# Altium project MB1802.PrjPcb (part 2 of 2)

## Sheet Audio_Codec.SchDoc: Audio_Codec
size A4; Date: Not used; ApprovedBy: Not used; CheckedBy: Not used; Author: Not used; CompanyName: STMicroelectronics; DrawnBy: Not used; Engineer: Not used; Organization: Not used; Address1: Not used; Address2: Not used; Address3: Not used; Address4: Not used; DocumentNumber: Not used; Revision: Not used; SheetNumber: 5; SheetTotal: 11
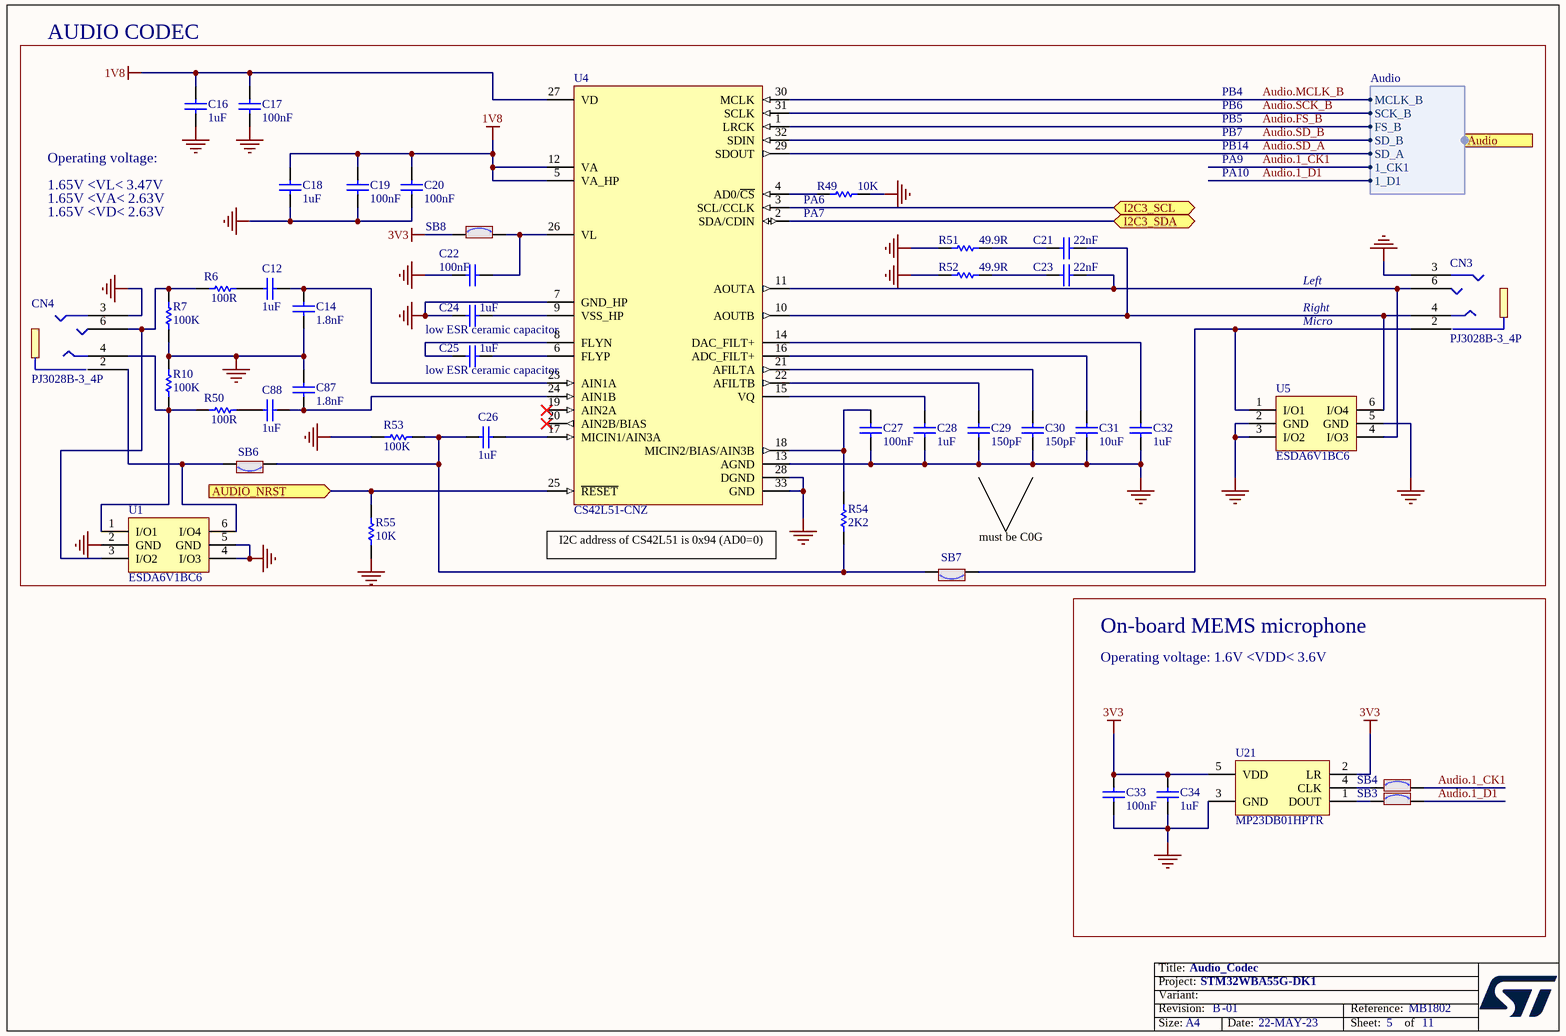
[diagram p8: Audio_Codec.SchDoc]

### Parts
C12  value 1uF  [C0402]  (hidden comment: Capacitor)
C14  value 1.8nF  [C0402]  (hidden comment: Capacitor)
C16  value 1uF  [C0402]  (hidden comment: Capacitor)
C17  value 100nF  [C0402]  (hidden comment: Capacitor)
C18  value 1uF  [C0402]  (hidden comment: Capacitor)
C19  value 100nF  [C0402]  (hidden comment: Capacitor)
C20  value 100nF  [C0402]  (hidden comment: Capacitor)
C21  value 22nF  [C0603]  (hidden comment: Capacitor)
C22  value 100nF  [C0402]  (hidden comment: Capacitor)
C23  value 22nF  [C0603]  (hidden comment: Capacitor)
C24  value 1uF  [C0402]  (hidden comment: Capacitor)
C25  value 1uF  [C0402]  (hidden comment: Capacitor)
C26  value 1uF  [C0402]  (hidden comment: Capacitor)
C27  value 100nF  [C0402]  (hidden comment: Capacitor)
C28  value 1uF  [C0402]  (hidden comment: Capacitor)
C29  value 150pF  [C0402]  (hidden comment: Capacitor)
C30  value 150pF  [C0402]  (hidden comment: Capacitor)
C31  value 10uF  [C0603]  (hidden comment: Capacitor)
C32  value 1uF  [C0402]  (hidden comment: Capacitor)
C33  value 100nF  [C0402]  (hidden comment: Capacitor)
C34  value 1uF  [C0402]  (hidden comment: Capacitor)
C87  value 1.8nF  [C0402]  (hidden comment: Capacitor)
C88  value 1uF  [C0402]  (hidden comment: Capacitor)
CN3  value PJ3028B-3_4P  [CON_PHONE-JACK-3P5_HY_PJ3028B]  (hidden comment: Jack_PJ3028B-3_4P)
CN4  value PJ3028B-3_4P  [CON_PHONE-JACK-3P5_HY_PJ3028B]  (hidden comment: Jack_PJ3028B-3_4P)
R6  value 100R  [R0402]  (hidden comment: Resistor)
R7  value 100K  [R0402]  (hidden comment: Resistor)
R10  value 100K  [R0402]  (hidden comment: Resistor)
R49  value 10K  [R0402]  (hidden comment: Resistor)
R50  value 100R  [R0402]  (hidden comment: Resistor)
R51  value 49.9R  [R0603]  (hidden comment: Resistor)
R52  value 49.9R  [R0603]  (hidden comment: Resistor)
R53  value 100K  [R0402]  (hidden comment: Resistor)
R54  value 2K2  [R0402]  (hidden comment: Resistor)
R55  value 10K  [R0402]  (hidden comment: Resistor)
SB3  (no value)  [SOLDER-BRIDGE_R0603-0R]
SB4  (no value)  [SOLDER-BRIDGE_R0603-0R]
SB6  (no value)  [SOLDER-BRIDGE_R0603-0R]
SB7  (no value)  [SOLDER-BRIDGE_R0603-0R]
SB8  SB_ON  [SOLDER-BRIDGE_R0603-0R]  (value not drawn)
U1  ESDA6V1BC6  [ESD_SOT23-6L]
U4  CS42L51-CNZ  [ICC_QFN32-EPAD_5X5_P050]
U5  ESDA6V1BC6  [ESD_SOT23-6L]
U21  value MP23DB01HPTR  [MIC_STM_MP23DB01MMTR]  (hidden comment: MP23DB01MMTR)

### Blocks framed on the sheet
AUDIO CODEC: C12 C14 C16-C32 C87 C88 CN3 CN4 R6 R7 R10 R49-R55 SB6-SB8 U1 U4 U5
On-board MEMS microphone: C33 C34 SB3 SB4 U21

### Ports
Audio (harness Audio), AUDIO_NRST (in), I2C3_SCL (bidir), I2C3_SDA (bidir)

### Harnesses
Audio: MCLK_B, 1_CK1, FS_B, SD_A, SCK_B, SD_B, 1_D1

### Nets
1V8: C16.2 C17.2 C18.2 C19.2 C20.2 U4.5(VA_HP) U4.12(VA) U4.27(VD)
3V3: C33.2 C34.1 SB8.1 U21.2(LR) U21.5(VDD)
GND: C14.1 C16.1 C17.1 C18.1 C19.1 C20.1 C22.2 C24.1 C27.1 C28.1 C29.1 C30.1 C31.1 C32.1 C33.1 C34.2 C87.2 CN3.3 CN4.3 R7.2 R10.1 R49.2 R51.2 R52.2 R53.2 R55.2 U1.2(GND) U1.4(I/O3) U1.5(GND) U4.7(GND_HP) U4.13(AGND) U4.28(DGND) U4.33(GND) U5.2(GND) U5.3(I/O2) U5.5(GND) U21.3(GND)
ARD_ADC.A4: U4.2(SDA/CDIN) ; port I2C3_SDA
ARD_ADC.A5: U4.3(SCL/CCLK) ; port I2C3_SCL
Audio.1_CK1: SB4.2 ; port Audio.1_CK1  [project net ARD.D9_TIM]
Audio.1_D1: SB3.2 ; port Audio.1_D1  [project net ARD.D6_TIM]
Audio.FS_B: U4.1(LRCK) ; port Audio.FS_B
Audio.MCLK_B: U4.30(MCLK) ; port Audio.MCLK_B
Audio.SCK_B: U4.31(SCLK) ; port Audio.SCK_B
Audio.SD_A: U4.29(SDOUT) ; port Audio.SD_A
Audio.SD_B: U4.32(SDIN) ; port Audio.SD_B
NetC12_1: C12.1 R6.2
NetC12_2: C12.2 C14.2 U4.23(AIN1A)
NetC21_1: C21.1 R51.1
NetC21_2: C21.2 CN3.4 U4.10(AOUTB) U5.6(I/O4)
NetC22_1: C22.1 SB8.2 U4.26(VL)
NetC23_1: C23.1 R52.1
NetC23_2: C23.2 CN3.6 U4.11(AOUTA) U5.4(I/O3)
NetC24_2: C24.2 U4.9(VSS_HP)
NetC25_1: C25.1 U4.8(FLYN)
NetC25_2: C25.2 U4.6(FLYP)
NetC26_1: C26.1 R53.1 R54.1 SB6.1 SB7.2
NetC26_2: C26.2 U4.17(MICIN1/AIN3A)
NetC27_2: C27.2 R54.2 U4.18(MICIN2/BIAS/AIN3B)
NetC28_2: C28.2 U4.15(VQ)
NetC29_2: C29.2 U4.22(AFILTB)
NetC30_2: C30.2 U4.21(AFILTA)
NetC31_2: C31.2 U4.16(ADC_FILT+)
NetC32_2: C32.2 U4.14(DAC_FILT+)
NetC87_1: C87.1 C88.2 U4.24(AIN1B)
NetC88_1: C88.1 R50.2
NetCN2_7: R55.1 U4.25(~{RESET}) ; port AUDIO_NRST
NetCN3_2: CN3.2 SB7.1 U5.1(I/O1)
NetCN4_2: CN4.2 SB6.2 U1.6(I/O4)
NetCN4_4: CN4.4 R10.2 R50.1 U1.1(I/O1)
NetCN4_6: CN4.6 R6.1 R7.1 U1.3(I/O2)
NetR49_1: R49.1 U4.4(AD0/~{CS})
NetSB3_1: SB3.1 U21.1(DOUT)
NetSB4_1: SB4.1 U21.4(CLK)

Not connected (* = marked no-connect by the designer): U4 19(AIN2A)* 20(AIN2B/BIAS)*

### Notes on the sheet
- PB6
- PB4
- (near C16) Operating voltage:
- PB14
- PB7
- PB5
- PA9
- PA10
- 1.65V <VL< 3.47V
- 1.65V <VA< 2.63V
- 1.65V <VD< 2.63V
- (near R49) PA6
- (near R49) PA7
- Left
- Right
- (near U4) low ESR ceramic capacitor
- Micro
- (near U4) I2C address of CS42L51 is 0x94 (AD0=0)
- (near SB7) must be C0G
- Operating voltage: 1.6V <VDD< 3.6V

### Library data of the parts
C12 C26 C88 = MCD-00095: Capacitor, MLCC, 1uF, 25V, X5R, +/-10%, 0402, T=0,5mm; Part_Preference: Recommended; Manufacturer: MURATA; Manufacturer_Part_Number: GRM155R61E105KA12; Alternate_Manufacturer_Part_Number: GRM155R60J105KE19; Order_Code_RS: 846-7287
C14 C87 = MCD-00694: Capacitor, MLCC, 1.8nF, 50V, X7R, +/-10%, 0402, T=0.5mm; Part_Preference: Recommended; Manufacturer: YAGEO; Manufacturer_Part_Number: CC0402KRX7R9BB182; Component_Country_Of_Origin: China; ShowFields: YES; ID: 3045
C16 C18 C24 C25 C28 C32 C34 = MCD-01722: Capacitor, 1uF, 10V, X5R, 10%, 0402, T=0.5mm; Manufacturer_Part_Number: CC0402KRX5R6BB105; Manufacturer: YAGEO; Provided_By: SUBCO
C17 C19 C20 C22 C27 C33 = MCD-00006: Capacitor, MLCC, 100nF, 16V, X7R, +/-10%, 0402, T=0.5mm; Part_Preference: Recommended; Manufacturer: YAGEO; Manufacturer_Part_Number: CC0402KRX7R7BB104; Partial_Alternate_Internal_Part_Number: MCD-03299; Order_Code_RS: 9402047; Component_Country_Of_Origin: China; ShowFields: YES; ID: 2474
C21 C23 = MCD-00555: Capacitor, MLCC, 22nF, 10%, 25V, X7R, 0603, T=0,8mm; Manufacturer_Part_Number: CC0603KRX7R8BB223; Manufacturer: YAGEO; Provided_By: SUBCO
C29 C30 = MCD-00672: Capacitor, MLCC, 150pF, 50V, NPO, 5%, 0402, T=0,5mm; Manufacturer_Part_Number: CC0402JRNPO9BN151; Manufacturer: YAGEO; Provided_By: SUBCO
C31 = MCD-00098: Capacitor, MLCC, 10uF, 6V3, X5R, 10%, 0603, T=0,8mm; Manufacturer_Part_Number: CC0603KRX5R5BB106; Manufacturer: YAGEO; Provided_By: SUBCO
CN3 CN4 = MCD-00263: Connector Jack Socket Stereo 3.5mm, 4 pins, RA, SMT, Black; Part_Preference: Recommended; Manufacturer: QIAOD
R6 R50 = MCD-00067: Resistor, 100R, 0402, +/- 1%, 1/16W; Part_Preference: Recommended; Manufacturer: YAGEO; Manufacturer_Part_Number: RC0402FR-07100RL; Component_Country_Of_Origin: China; ShowFields: YES; ID: 2527
R7 R10 R53 = MCD-00059: Resistor,100K,0402,1%,1/16W; Manufacturer_Part_Number: RC0402FR-07100KL; Manufacturer: YAGEO; Alternate_Manufacturer_Part_Number: RT0402FRE07100KL; Provided_By: SUBCO
R49 R55 = MCD-00053: Resistor,10K,0402,1%,1/16W; Manufacturer_Part_Number: RC0402FR-0710KL; Manufacturer: YAGEO; Provided_By: SUBCO
R51 R52 = MCD-00564: Resistor,49R9,0603,1%,1/10W; Manufacturer_Part_Number: RC0603FR-0749R9L; Manufacturer: YAGEO; Provided_By: SUBCO
R54 = MCD-00057: Resistor,2K2,0402,1%,1/16W; Part_Preference: Recommended; Manufacturer: YAGEO; Manufacturer_Part_Number: RC0402FR-072K2L
SB3 SB4 SB6 SB7 = MCD-00071: Solder Bridge ON; Part_Type: Mechanical; Provided_By: Subcon; Initial_Board_Reference: mb1274
SB8 = MCD-00071: Solder Bridge ON; Part_Type: Mechanical; Manufacturer_Part_Number: RC0603JR-070RL; Manufacturer: YAGEO; Provided_By: SUBCO
U1 U5 = MCD-00247: Quad Bidir ESD protection; BMS_Part_Number: 9179038; Part_Preference: Recommended; Part_Type: Diode; Manufacturer: STMICROELECTRONICS; Manufacturer_HQ_COO: EU
U4 = MCD-00265: Low-Power, Stereo Codec with Headphone Amp; Part_Type: IC; Manufacturer: CIRRUS LOGIC; Provided_By: SUBCO
U21 = MCD-02122: MEMS sensors , omnidirectionnal digital microphone; Part_Preference: Recommended; Part_Type: IC; Manufacturer: STMICROELECTRONICS; Component_Country_Of_Origin: China

## Sheet Joystick_&_Reset.SchDoc: Joystick_&_RESET
size A4; Date: Not used; ApprovedBy: Not used; CheckedBy: Not used; Author: Not used; CompanyName: STMicroelectronics; DrawnBy: Not used; Engineer: Not used; Organization: Not used; Address1: Not used; Address2: Not used; Address3: Not used; Address4: Not used; DocumentNumber: Not used; Revision: Not used; SheetNumber: 4; SheetTotal: 11
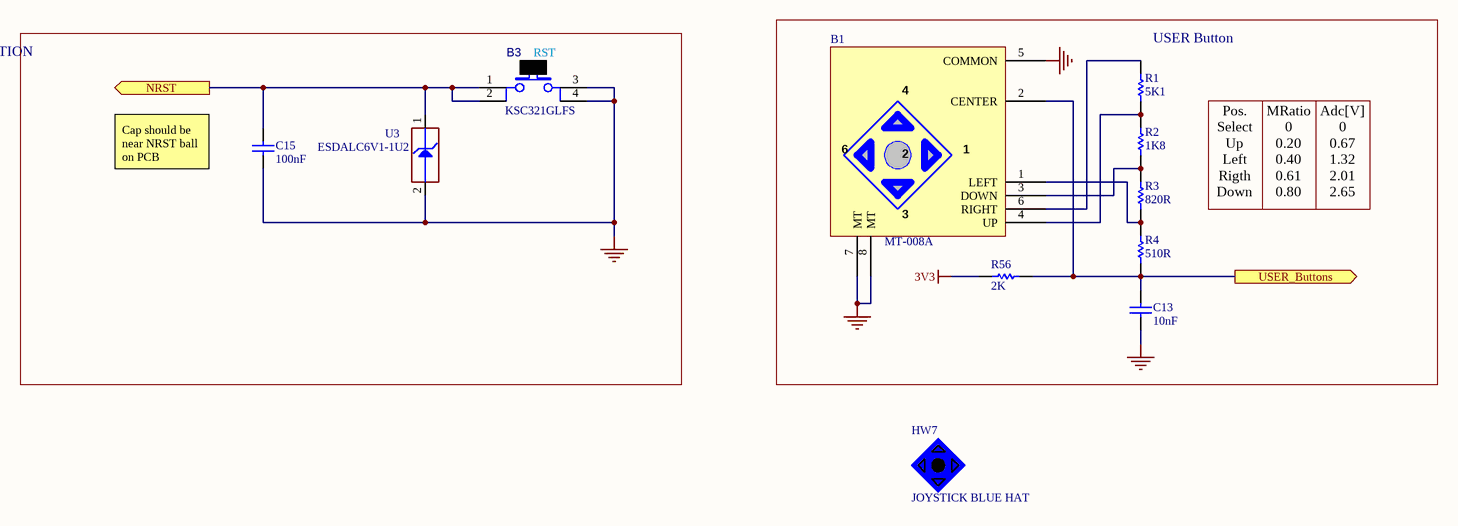
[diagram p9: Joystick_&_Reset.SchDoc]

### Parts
B1  value MT-008A  [SWI_XIEJIA_MT-008A_6P]  (hidden comment: Joystick MT-008A_M)
B3  value KSC321GLFS  [SWI_C&K_KSC321GLFS_BLACK]  (hidden comment: SW_BLACK_KSC321GLFS)
C13  value 10nF  [C0402]  (hidden comment: Capacitor)
C15  value 100nF  [C0402]  (hidden comment: Capacitor)
HW7  value JOYSTICK BLUE HAT  (hidden comment: JOYSTICK_BLUE_HAT)  (mechanical)
R1  value 5K1  [R0402]  (hidden comment: Resistor)
R2  value 1K8  [R0402]  (hidden comment: Resistor)
R3  value 820R  [R0402]  (hidden comment: Resistor)
R4  value 510R  [R0402]  (hidden comment: Resistor)
R56  value 2K  [R0402]  (hidden comment: Resistor)
U3  value ESDALC6V1-1U2  [ESD_ST0201]

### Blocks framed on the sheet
RESET FUNCTION: B3 C15 U3
USER Button: B1 C13 R1-R4 R56

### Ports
NRST (out), USER_Buttons (out)

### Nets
3V3: R56.1
GND: B1.5(COMMON) B1.7(MT) B1.8(MT) B3.3 B3.4 C13.1 C15.1 U3.2(GND)
ARD_ADC.A1: B1.2(CENTER) C13.2 R4.1 R56.2 ; port USER_Buttons
NRST: B3.1 B3.2 C15.2 U3.1(IO1) ; port NRST
NetB1_1: B1.1(LEFT) R3.1 R4.2
NetB1_3: B1.3(DOWN) R2.1 R3.2
NetB1_4: B1.4(UP) R1.1 R2.2
NetB1_6: B1.6(RIGHT) R1.2

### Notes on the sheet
- (near B3) RST
- Cap should be near NRST ball on PCB
- Pos.
  Select
  Up
  Left
  Rigth
  Down
- MRatio
  0
  0.20
  0.40
  0.61
  0.80
- Adc[V]
  0
  0.67
  1.32
  2.01
  2.65

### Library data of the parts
B1 = MCD-00132: Joystick, 4 dir, 1 OK; BMS_Part_Number: 9180124; Part_Preference: Recommended; Part_Type: Misc; Manufacturer: XIEJIA ELECTRONICS
B3 = MCD-00175: Switch HW BLACK High3.5mm 2Newtons; Part_Type: Misc; Manufacturer: C&K; Provided_By: SUBCO; Initial_Board_Reference: MB1274
C13 = MCD-00011: Capacitor, MLCC, 10nF, 16V, X7R, +/-10%, 0402, T=0.5mm; Manufacturer_Part_Number: CC0402KRX7R7BB103; Manufacturer: YAGEO; Part_Preference: Recommended; Provided_By: SUBCO; ECCN_US: EAR99; ECCN_EU: NEC; Order_Code_RS: 669-8688
C15 = MCD-00006: Capacitor, MLCC, 100nF, 16V, X7R, 10%, 0402, T=0.5mm; Manufacturer_Part_Number: CC0402KRX7R7BB104; Manufacturer: YAGEO; Provided_By: SUBCO; Initial_Board_Reference: MB1274
HW7 = MCD-01337: Joystick Blue Hat; Part_Type: Misc; Part_Preference: Alternate; Manufacturer: JIUBABA; Manufacturer_Part_Number: PB-504; Component_Country_Of_Origin: Unknown; Alternate_EMS: A; ShowFields: YES; ID: 3437
R1 = MCD-00333: Resistor, 5K1, 0402, +/-1%, 1/16W; Manufacturer_Part_Number: RC0402FR-075K1L; Manufacturer: YAGEO; Part_Preference: Recommended; ECCN_US: EAR99; ECCN_EU: NEC; Provided_By: SUBCO
R2 = MCD-00409: Resistor, 1K8, 0402, +/-1%, 1/16W; Manufacturer_Part_Number: RC0402FR-071K8L; Manufacturer: YAGEO; Part_Preference: Recommended; ECCN_US: EAR99; ECCN_EU: NEC; Provided_By: SUBCO
R3 = MCD-00527: Resistor, 820R, 0402, +/-1%, 1/16W; Manufacturer_Part_Number: RC0402FR-07820RL; Manufacturer: YAGEO; Part_Preference: Recommended; ECCN_US: EAR99; ECCN_EU: NEC; Provided_By: SUBCO
R4 = MCD-00064: Resistor, 510R, 0402, +/-1%, 1/16W; Manufacturer_Part_Number: RC0402FR-07510RL; Manufacturer: YAGEO; Part_Preference: Recommended; ECCN_US: EAR99; ECCN_EU: NEC; Provided_By: SUBCO
R56 = MCD-00419: Resistor, 2K, 0402, +/-1%, 1/16W; Manufacturer_Part_Number: RC0402FR-072KL; Manufacturer: YAGEO; Part_Preference: Recommended; ECCN_US: EAR99; ECCN_EU: NEC; Provided_By: SUBCO
U3 = MCD-00170: ESD protection 6V1; Part_Type: Diode; Manufacturer: STMICROELECTRONICS; ECCN_US: EAR99; ECCN_EU: NEC; Provided_By: Subcon; Initial_Board_Reference: MB1274

## Sheet Arduino.SchDoc: Arduino
size A4; Date: Not used; ApprovedBy: Not used; CheckedBy: Not used; Author: Not used; CompanyName: STMicroelectronics; DrawnBy: Not used; Engineer: Not used; Organization: Not used; Address1: Not used; Address2: Not used; Address3: Not used; Address4: Not used; DocumentNumber: Not used; Revision: Not used; SheetNumber: 6; SheetTotal: 11
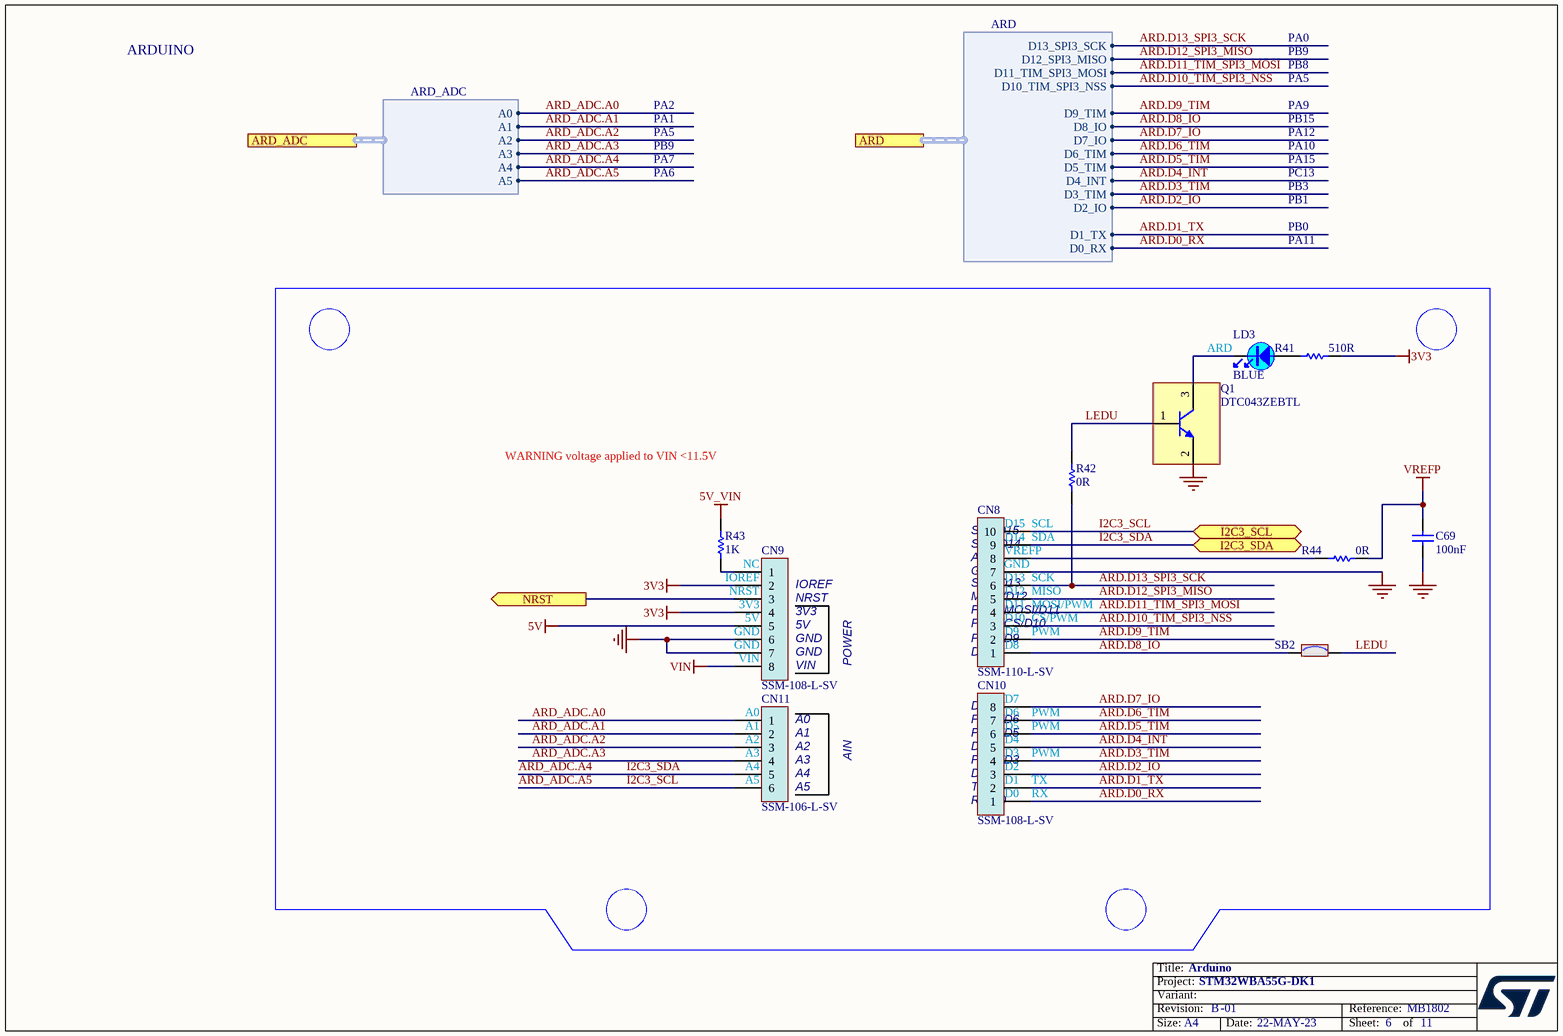
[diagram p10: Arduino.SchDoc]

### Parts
C69  value 100nF  [C0402]
CN8  value SSM-110-L-SV  [CON_SAMTEC_SSM-110-L-SV]  (hidden comment: Socket 10x1)
CN9  value SSM-108-L-SV  [CON_SAMTEC_SSM-108-L-SV]  (hidden comment: Socket 8x1)
CN10  value SSM-108-L-SV  [CON_SAMTEC_SSM-108-L-SV]  (hidden comment: Socket 8x1)
CN11  value SSM-106-L-SV  [CON_SAMTEC_SSM-106-L-SV]  (hidden comment: Socket 6x1)
LD3  value BLUE  [LED_0603_VISHAY_VLMB1300-GS08_BLUE_1A2K_H0P8]  (hidden comment: LED_blue)
Q1  DTC043ZEBTL  [NPN_SOT416-FL_EMT3F_1616_SC89]
R41  value 510R  [R0402]  (hidden comment: Resistor)
R42  value 0R  [R0402]
R43  value 1K  [R0402]  (hidden comment: Resistor)
R44  value 0R  [R0402]
SB2  (no value)  [SOLDER-BRIDGE_R0603-0R]

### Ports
ARD (harness ARD), ARD_ADC (harness ARD_ADC), I2C3_SCL (bidir), I2C3_SDA (bidir), NRST (out)

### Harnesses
ARD: D0_RX, D1_TX, D2_IO, D3_TIM, D4_INT, D5_TIM, D6_TIM, D7_IO, D8_IO, D9_TIM, D10_TIM_SPI3_NSS, D11_TIM_SPI3_MOSI, D12_SPI3_MISO, D13_SPI3_SCK
ARD_ADC: A0, A1, A2, A3, A4, A5

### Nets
3V3: CN9.2 CN9.4 R41.1
5V: CN9.5
5V_VIN: R43.2
GND: C69.2 CN8.7 CN9.6 CN9.7 Q1.2(E)
VIN: CN9.8
VREFP: C69.1 R44.2  [project net V1]
ARD.D0_RX: CN10.1 ; port ARD.D0_RX
ARD.D1_TX: CN10.2 ; port ARD.D1_TX
ARD.D2_IO: CN10.3 ; port ARD.D2_IO
ARD.D3_TIM: CN10.4 ; port ARD.D3_TIM
ARD.D4_INT: CN10.5 ; port ARD.D4_INT
ARD.D5_TIM: CN10.6 ; port ARD.D5_TIM
ARD.D6_TIM: CN10.7 ; port ARD.D6_TIM
ARD.D7_IO: CN10.8 ; port ARD.D7_IO
ARD.D8_IO: CN8.1 SB2.1 ; port ARD.D8_IO
ARD.D9_TIM: CN8.2 ; port ARD.D9_TIM
ARD.D10_TIM_SPI3_NSS: CN8.3 CN11.3 ; port ARD.D10_TIM_SPI3_NSS, port ARD_ADC.A2  [also labelled ARD_ADC.A2]
ARD.D11_TIM_SPI3_MOSI: CN8.4 ; port ARD.D11_TIM_SPI3_MOSI
ARD.D12_SPI3_MISO: CN8.5 CN11.4 ; port ARD.D12_SPI3_MISO, port ARD_ADC.A3  [also labelled ARD_ADC.A3]
ARD.D13_SPI3_SCK: CN8.6 R42.1 ; port ARD.D13_SPI3_SCK
ARD_ADC.A0: CN11.1 ; port ARD_ADC.A0
ARD_ADC.A1: CN11.2 ; port ARD_ADC.A1
ARD_ADC.A4: CN8.9 CN11.5 ; port I2C3_SDA, port ARD_ADC.A4  [also labelled I2C3_SDA]
ARD_ADC.A5: CN8.10 CN11.6 ; port I2C3_SCL, port ARD_ADC.A5  [also labelled I2C3_SCL]
LEDU: Q1.1(B) R42.2 SB2.2
NRST: CN9.3 ; port NRST
NetCN8_8: CN8.8 R44.1
NetCN9_1: CN9.1 R43.1
NetLD3_1: LD3.1 R41.2
NetLD3_2: LD3.2 Q1.3(C)

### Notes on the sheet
- PA0
- ARDUINO
- PA2
- PA9
- PB8
- PA5
- PB9
- PA6
- PA7
- PA1
- PA15
- PA10
- PC13
- PB15
- PA12
- PB0
- PA11
- PB3
- PB1
- (near LD3) ARD
- WARNING voltage applied to VIN <11.5V
- (near CN9) NC
- (near CN9) IOREF
- (near CN8) SDA/D14
- (near CN8) SCL/D15
- (near CN8) SCK/D13
- (near CN8) AVDD
- (near CN8) GND
- (near CN8) VREFP
- (near CN8) D13
- (near CN8) D14
- (near CN8) D15
- SCL
- (near CN8) SDA
- (near CN8) SCK
- (near CN9) NRST
- (near CN9) 3V3
- (near CN9) 5V
- (near CN9) GND
- (near CN8) D8
- (near CN8) PWM/D9
- (near CN8) PWM/CS/D10
- (near CN8) MISO/D12
- (near CN8) PWM/MOSI/D11
- (near CN8) D9
- (near CN8) D10
- (near CN8) D11
- (near CN8) D12
- (near CN8) MISO
- (near CN8) MOSI/PWM
- (near CN8) CS/PWM
- (near CN8) PWM
- (near CN9) VIN
- (near CN11) A0
- POWER
- (near CN10) D7
- (near CN10) D6
- (near CN10) PWM
- (near CN11) A1
- (near CN11) A2
- (near CN11) A3
- (near CN11) A4
- (near CN11) A5
- AIN
- (near CN10) TX/D1
- (near CN10) D2
- (near CN10) D4
- (near CN10) PWM/D3
- (near CN10) PWM/D5
- (near CN10) PWM/D6
- (near CN10) D5
- (near CN10) D3
- (near CN10) D1
- (near CN10) TX
- (near CN10) RX/D0
- (near CN10) D0
- (near CN10) RX

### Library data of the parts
C69 = MCD-00006: Capacitor,100nF,16V,X7R,10%,0402; Manufacturer_Part_Number: CC0402KRX7R7BB104; Manufacturer: YAGEO; Provided_By: Subcon; Initial_Board_Reference: mb1274
CN8 = MCD-02342: Socket, 10x1, 2.54mm, VR, SMT, Height 7.37mm; Part_Type: Connector; Part_Preference: Recommended; Manufacturer: SAMTEC; Order_Code_RS: 765-5420
CN9 CN10 = MCD-02345: Socket, 8x1, 2.54mm, VR, SMT, Height 7.37mm; Part_Type: Connector; Part_Preference: Recommended; Manufacturer: SAMTEC; Order_Code_RS: 765-5411
CN11 = MCD-02346: Socket, 6x1, 2.54mm, VR, SMT, Height 7.37mm; Part_Type: Connector; Part_Preference: Recommended; Manufacturer: SAMTEC; Order_Code_RS: 765-5408
LD3 = MCD-00584: LED Blue, 0603 SMD, 3.3 V Forward Voltage; Part_Type: Display; Part_Preference: Recommended; Manufacturer: VISHAY; Manufacturer_Part_Number: VLMB1300-GS08; Order_Code_RS: 7730430; Component_Country_Of_Origin: China; ShowFields: YES; ID: 3160
Q1 = MCD-00280: Buffer transistor; Part_Type: IC; Manufacturer: ROHM; Provided_By: Subcon; Initial_Board_Reference: MB1329
R41 = MCD-00064: Resistor,510R,0402,1%,1/16W; Manufacturer_Part_Number: RC0402FR-07510RL; Manufacturer: YAGEO; Provided_By: Subcon; Initial_Board_Reference: MB1274
R42 R44 = MCD-00052: Resistor,0R,0402,5%,1/16W; Manufacturer_Part_Number: RC0402JR-070RL; Manufacturer: YAGEO; Provided_By: Subcon; Initial_Board_Reference: mb1274
R43 = MCD-00061: Resistor,1K,0402,1%,1/16W; Manufacturer_Part_Number: RC0402FR-071KL; Manufacturer: YAGEO; Provided_By: Subcon; Initial_Board_Reference: mb1274
SB2 = MCD-00071: as SB3 on sheet Audio_Codec

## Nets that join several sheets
1V8: Board_Power (C86.2 TP2.1 U19.5), Audio_Codec (8 pins)
3V3: Board_Power (7 pins), External_Debug_Interface (CN14.3 CN15.1), OLED (C74.1 U13.8), STLink_V3EC (LNK1.1), STMod+ (C70.2 JP2.2 JP3.1 U12.2), Audio_Codec (5 pins), Joystick_&_Reset (R56.1), Arduino (CN9.2 CN9.4 R41.1)
3V6: Board_Power (C77.1 U16.5), OLED (C75.1 U13.5)
5V: Board_Power (11 pins), STLink_V3EC (R22.2), STMod+ (CN12.6 CN12.15 JP3.3), Arduino (CN9.5)
5V_STLK: Board_Power (JP4.1), STLink_V3EC (6 pins)
5V_VIN: Board_Power (C84.2 JP4.3 U20.2 U20.4), STLink_V3EC (D2.1), Arduino (R43.2)
GND: Board_Power (17 pins), External_Debug_Interface (7 pins), OLED (10 pins), STLink_V3EC (103 pins), MCU (34 pins), STMod+ (6 pins), Audio_Codec (37 pins), Joystick_&_Reset (8 pins), Arduino (5 pins)
V1: Board_Power (JP5.1), MCU (32 pins), Arduino (C69.1 R44.2)
VBUS_STLK: Board_Power (JP4.7), STLink_V3EC (12 pins)
VIN: Board_Power (C83.2 U20.3), Arduino (CN9.8)
ARD.D0_RX: MCU (CN2.37), STMod+ (U12.7), Arduino (CN10.1)
ARD.D1_TX: MCU (CN2.29), STMod+ (U12.4), Arduino (CN10.2)
ARD.D2_IO: MCU (CN2.9), STMod+ (U12.12), Arduino (CN10.3)
ARD.D3_TIM: External_Debug_Interface (CN14.8 CN15.6 U14.3), STLink_V3EC (R17.2), MCU (CN2.13), STMod+ (CN12.20), Arduino (CN10.4)
ARD.D4_INT: MCU (CN2.46), STMod+ (CN12.11), Arduino (CN10.5)
ARD.D5_TIM: External_Debug_Interface (CN14.10 CN15.8 U14.4), STLink_V3EC (R19.2), MCU (CN2.15), STMod+ (CN12.19), Arduino (CN10.6)
ARD.D6_TIM: MCU (CN2.45), STMod+ (CN12.17), Audio_Codec (SB3.2), Arduino (CN10.7)
ARD.D7_IO: MCU (JP7.3), STMod+ (CN12.18), Arduino (CN10.8)
ARD.D8_IO: MCU (CN2.25), STMod+ (U12.15), Arduino (CN8.1 SB2.1)
ARD.D9_TIM: MCU (CN1.29), STMod+ (CN12.12), Audio_Codec (SB4.2), Arduino (CN8.2)
ARD.D10_TIM_SPI3_NSS: MCU (CN1.42), STMod+ (U12.1), Arduino (CN8.3 CN11.3)
ARD.D11_TIM_SPI3_MOSI: OLED (U13.15), MCU (CN2.48), STMod+ (U12.6), Arduino (CN8.4)
ARD.D12_SPI3_MISO: OLED (U13.13), MCU (CN2.27), STMod+ (U12.9), Arduino (CN8.5 CN11.4)
ARD.D13_SPI3_SCK: OLED (U13.14), MCU (CN1.44), STMod+ (U12.14), Arduino (CN8.6 R42.1)
ARD_ADC.A0: MCU (CN1.36 SB10.2), STMod+ (CN12.13), Arduino (CN11.1)
ARD_ADC.A1: MCU (CN1.38), STMod+ (CN12.14), Joystick_&_Reset (B1.2 C13.2 R4.1 R56.2), Arduino (CN11.2)
ARD_ADC.A4: MCU (CN1.24 R9.1 SB5.2), STMod+ (CN12.10 CN13.2), Audio_Codec (U4.2), Arduino (CN8.9 CN11.5)
ARD_ADC.A5: MCU (CN1.26 R8.1), STMod+ (CN12.7 CN13.1), Audio_Codec (U4.3), Arduino (CN8.10 CN11.6)
Audio.FS_B: MCU (CN2.43), Audio_Codec (U4.1)
Audio.MCLK_B: MCU (CN2.11 SB9.1), Audio_Codec (U4.30)
Audio.SCK_B: MCU (CN2.39), Audio_Codec (U4.31)
Audio.SD_A: MCU (CN2.35), Audio_Codec (U4.29)
Audio.SD_B: MCU (CN2.41), Audio_Codec (U4.32)
JNTRST: External_Debug_Interface (CN15.9 U15.4), MCU (SB9.2)
MCU.CTS: STLink_V3EC (U6.N13), MCU (SB5.1)
MCU.RTS: STLink_V3EC (U6.N14), MCU (SB10.1)
MCU.SWCLK: External_Debug_Interface (CN14.6 CN14.9 CN15.4 U14.1), STLink_V3EC (R18.2), MCU (CN1.15)
MCU.SWDIO: External_Debug_Interface (CN14.4 CN15.2 U14.5), STLink_V3EC (R16.2), MCU (CN1.13)
MCU.VCP_RX: External_Debug_Interface (CN14.13 U15.3), STLink_V3EC (R21.2 R57.2), MCU (CN1.45)
MCU.VCP_TX: External_Debug_Interface (CN14.14 U15.1), STLink_V3EC (R20.2 R58.2), MCU (CN1.47)
NetCN2_7: MCU (CN2.7), Audio_Codec (R55.1 U4.25)
NRST: External_Debug_Interface (CN14.12 CN15.10 U15.5), STLink_V3EC (R24.2), MCU (CN1.12), Joystick_&_Reset (B3.1 B3.2 C15.2 U3.1), Arduino (CN9.3)
OLED.CS: OLED (U13.11), MCU (CN1.9 JP6.1)
OLED.RST: OLED (U13.12), MCU (JP7.1)

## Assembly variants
WBA55C: not fitted C46 C47 CN7 CN15 JP1 R39 R40 R42 R42 R44 SB1 SB5 SB6 SB9 SB10 U10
